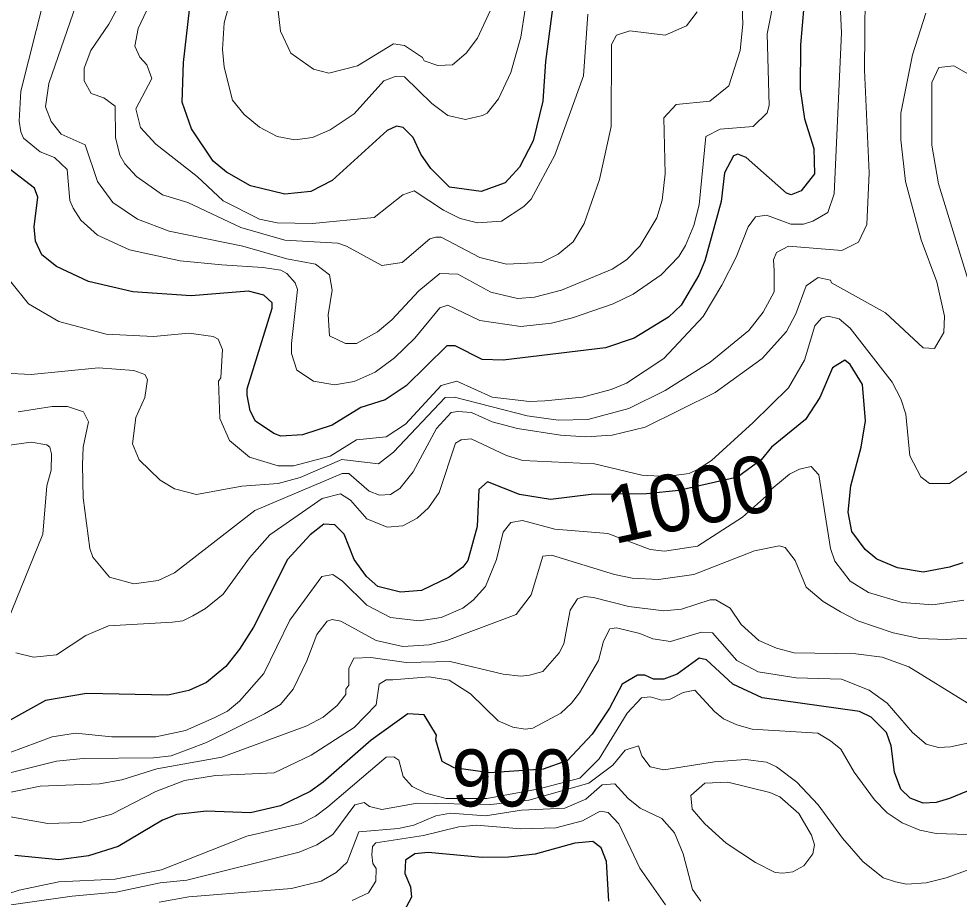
# Model space of a CAD drawing. Extents: x 423 to 448.8, y 7456.3 to 7484.
# Drawn here: x 424.12 to 425.439, y 7464.022 to 7465.258 of the extents above; entities that cross this region are included whole.
import ezdxf
from ezdxf.enums import TextEntityAlignment as Align

# ---------------------------------------------------------------- set-up
doc = ezdxf.new("R2010")
doc.units = 0
doc.header["$LTSCALE"] = 0.032
doc.layers.add('1', color=7, linetype='Continuous', lineweight=25)
doc.layers.add('2', color=7, linetype='Continuous', lineweight=13)
doc.layers.add('61', color=7, linetype='Continuous')

msp = doc.modelspace()

# ---------------------------------------------------------------- linework, layer by layer
at = {"layer": '1'}
for points in [[(425.2237, 7465.303), (425.2168, 7465.221), (425.216, 7465.1591), (425.2222, 7465.1173), (425.2353, 7465.0756), (425.2361, 7465.04), (425.2175, 7465.016), (425.2036, 7465.0106), (425.1967, 7465.0129), (425.1402, 7465.0631), (425.1286, 7465.0678), (425.1224, 7465.0655), (425.11, 7465.0415), (425.1054, 7465.0013), (425.0822, 7464.9178), (425.0737, 7464.8977), (425.0489, 7464.8559), (425.0311, 7464.8388), (424.9832, 7464.8095), (424.943, 7464.7956), (424.7991, 7464.7785), (424.7697, 7464.7793), (424.7318, 7464.7987), (424.7202, 7464.7987), (424.663, 7464.7422), (424.6336, 7464.7229), (424.5996, 7464.712), (424.5593, 7464.6873), (424.5176, 7464.6734), (424.4874, 7464.6718), (424.4774, 7464.6756), (424.4518, 7464.6927), (424.4441, 7464.7074), (424.4402, 7464.7291), (424.4402, 7464.7383), (424.475, 7464.8513), (424.475, 7464.859), (424.4634, 7464.8698), (424.4418, 7464.8752), (424.3613, 7464.869), (424.2794, 7464.8745), (424.2175, 7464.8891), (424.1726, 7464.91), (424.1517, 7464.9263), (424.1432, 7464.9456), (424.1409, 7464.9657), (424.1463, 7465.0075), (424.1416, 7465.0198), (424.1076, 7465.0462)], [(424.871, 7465.2906), (424.8587, 7465.1978), (424.8548, 7465.1421), (424.8416, 7465.0864), (424.8223, 7465.0493), (424.8022, 7465.0276), (424.7682, 7465.0152), (424.7241, 7465.0214), (424.6978, 7465.0477), (424.6839, 7465.0678), (424.673, 7465.091), (424.6591, 7465.1049), (424.6498, 7465.1072), (424.6366, 7465.1011), (424.5593, 7465.0307), (424.5292, 7465.0152), (424.4928, 7465.0113), (424.4449, 7465.023), (424.4108, 7465.0423), (424.3922, 7465.0577), (424.3621, 7465.1034), (424.3489, 7465.1405), (424.3505, 7465.1962), (424.359, 7465.2705)], [(425.4442, 7464.4939), (425.4256, 7464.4877), (425.3885, 7464.4808), (425.3529, 7464.4869), (425.3235, 7464.4993), (425.3073, 7464.5125), (425.2887, 7464.538), (425.2833, 7464.5651), (425.2872, 7464.6022), (425.3019, 7464.6563), (425.308, 7464.6935), (425.3034, 7464.7445), (425.2864, 7464.7723), (425.2786, 7464.7785), (425.2616, 7464.7677), (425.2438, 7464.726), (425.2237, 7464.695), (425.1758, 7464.6563), (425.1614, 7464.6384), (425.128, 7464.614), (425.046, 7464.5953), (425.0006, 7464.5906), (424.9229, 7464.5898), (424.8656, 7464.5828), (424.8223, 7464.5898), (424.7775, 7464.6076), (424.7651, 7464.5968), (424.7628, 7464.545), (424.7496, 7464.497), (424.7426, 7464.4877), (424.7233, 7464.4738), (424.6846, 7464.4552), (424.6553, 7464.4529), (424.6235, 7464.4606), (424.6073, 7464.4746), (424.5903, 7464.4986), (424.5763, 7464.5341), (424.5632, 7464.5473), (424.5477, 7464.5481), (424.5284, 7464.5333), (424.4967, 7464.4986), (424.4487, 7464.4034), (424.4294, 7464.3725), (424.41, 7464.3485), (424.383, 7464.326), (424.3582, 7464.3145), (424.3289, 7464.3083), (424.2144, 7464.3106), (424.1571, 7464.3005), (424.069, 7464.2518)], [(425.0744, 7464.3601), (425.0435, 7464.3377), (425.025, 7464.3307), (425.0102, 7464.3307), (424.9979, 7464.3361), (424.9878, 7464.3361), (424.9662, 7464.3237), (424.9484, 7464.2897), (424.9244, 7464.2533), (424.8896, 7464.2162), (424.8555, 7464.2043), (424.7801, 7464.1989), (424.7304, 7464.2061), (424.7139, 7464.2151), (424.7046, 7464.2454), (424.7055, 7464.2518), (424.6885, 7464.2804), (424.6653, 7464.282), (424.6142, 7464.2448), (424.5469, 7464.186), (424.5284, 7464.1729), (424.4866, 7464.1528), (424.4449, 7464.1428), (424.383, 7464.1451), (424.3412, 7464.1404), (424.3211, 7464.1327), (424.2592, 7464.0955), (424.2175, 7464.0824), (424.1757, 7464.077), (424.1138, 7464.0832)], [(425.4813, 7464.1861), (425.4256, 7464.1629), (425.4071, 7464.1575), (425.3885, 7464.1567), (425.3707, 7464.1636), (425.3575, 7464.176), (425.3483, 7464.2), (425.3436, 7464.2371), (425.3374, 7464.2557), (425.3157, 7464.2773), (425.2995, 7464.2851), (425.1626, 7464.3044), (425.1216, 7464.3237), (425.0845, 7464.3578), (425.0744, 7464.3601)], [(424.9476, 7464.019), (424.9445, 7464.0747), (424.9368, 7464.094), (424.9252, 7464.1025), (424.8997, 7464.1002), (424.844, 7464.0847), (424.8069, 7464.0809), (424.7697, 7464.0801), (424.6939, 7464.0871), (424.6754, 7464.0855), (424.6622, 7464.0763), (424.6614, 7464.0577), (424.6692, 7464.0391), (424.6707, 7464.0244), (424.6599, 7464.0043)]]:
    msp.add_lwpolyline(points, dxfattribs=at)
at = {"layer": '2'}
for points in [[(424.4835, 7465.2689), (424.4866, 7465.2403), (424.5013, 7465.2093), (424.533, 7465.1869), (424.5547, 7465.1815), (424.5949, 7465.1915), (424.6452, 7465.2225), (424.6606, 7465.2202), (424.6862, 7465.2032), (424.6885, 7465.1985), (424.7078, 7465.1923), (424.728, 7465.1931), (424.7473, 7465.2094), (424.7635, 7465.2303), (424.8331, 7465.3811)], [(424.4247, 7465.3138), (424.4077, 7465.2519), (424.4054, 7465.2148), (424.4077, 7465.19), (424.4193, 7465.1436), (424.4356, 7465.1235), (424.4573, 7465.1057), (424.482, 7465.0926), (424.5068, 7465.0879), (424.5315, 7465.091), (424.5563, 7465.1018), (424.5903, 7465.1243), (424.632, 7465.1707), (424.6475, 7465.1769), (424.6606, 7465.1761), (424.6993, 7465.139), (424.7218, 7465.1219), (424.7465, 7465.1165), (424.7705, 7465.1219), (424.7767, 7465.125), (424.7929, 7465.1452), (424.8099, 7465.1823), (424.8239, 7465.2318), (424.8424, 7465.3501)], [(425.308, 7465.3416), (425.3065, 7465.1854), (425.3127, 7465.0415), (425.3096, 7464.9688), (425.298, 7464.9441), (425.2748, 7464.9325), (425.1997, 7464.9386), (425.1827, 7464.9294), (425.1789, 7464.9193), (425.1796, 7464.9039), (425.1796, 7464.8745), (425.1641, 7464.8458), (425.1441, 7464.8203), (425.0899, 7464.7755), (425.0265, 7464.736), (424.9755, 7464.7105), (424.9182, 7464.695), (424.8765, 7464.6942), (424.8332, 7464.7004), (424.7311, 7464.7267), (424.7179, 7464.7259), (424.6452, 7464.6494), (424.6243, 7464.6331), (424.5727, 7464.6389), (424.5145, 7464.6138), (424.4835, 7464.6053), (424.4325, 7464.6014), (424.3691, 7464.5898), (424.3381, 7464.5976), (424.318, 7464.6099), (424.2886, 7464.6385), (424.2793, 7464.6609), (424.284, 7464.6981), (424.2963, 7464.7259), (424.3002, 7464.7515), (424.2964, 7464.7584), (424.2809, 7464.7638), (424.2314, 7464.7677), (424.137, 7464.7584), (424.0999, 7464.76)], [(425.2709, 7465.3091), (425.274, 7465.238), (425.2639, 7465.0121), (425.2547, 7464.9858), (425.2338, 7464.9734), (425.2206, 7464.9696), (425.2029, 7464.9696), (425.1688, 7464.9819), (425.1534, 7464.9796), (425.1433, 7464.9657), (425.1263, 7464.9232), (425.1062, 7464.8837), (425.0799, 7464.8396), (425.025, 7464.7809), (424.9724, 7464.746), (424.9507, 7464.7375), (424.9105, 7464.7267), (424.8579, 7464.7213), (424.8362, 7464.7205), (424.7837, 7464.7267), (424.7341, 7464.7491), (424.7124, 7464.7429), (424.6622, 7464.6888), (424.6351, 7464.671), (424.5934, 7464.6664), (424.5563, 7464.6439), (424.5052, 7464.63), (424.4835, 7464.63), (424.4433, 7464.6424), (424.4154, 7464.6656), (424.4015, 7464.6966), (424.4, 7464.7492), (424.4031, 7464.7538), (424.4054, 7464.7932), (424.3992, 7464.8079), (424.3923, 7464.8118), (424.3582, 7464.8164), (424.3087, 7464.8118), (424.2422, 7464.8149), (424.1757, 7464.8327), (424.1331, 7464.8574), (424.1084, 7464.8884)], [(424.8973, 7464.9448), (424.8764, 7464.9271), (424.8533, 7464.9154), (424.8038, 7464.9131), (424.7666, 7464.9224), (424.7125, 7464.951), (424.7048, 7464.951), (424.6962, 7464.9487), (424.6576, 7464.9154), (424.629, 7464.9115), (424.5795, 7464.9386), (424.5671, 7464.9425), (424.4928, 7464.9471), (424.431, 7464.9649), (424.3567, 7464.9997), (424.3211, 7465.0106), (424.2847, 7465.0361), (424.2685, 7465.0539), (424.2615, 7465.0663), (424.2553, 7465.091), (424.2546, 7465.1351), (424.2391, 7465.1467), (424.2213, 7465.1529), (424.2113, 7465.1707), (424.2113, 7465.1885), (424.2205, 7465.2132), (424.2461, 7465.2504), (424.2724, 7465.2999)], [(425.134, 7465.2999), (425.1355, 7465.2504), (425.1317, 7465.2132), (425.1162, 7465.1637), (425.0891, 7465.1421), (425.042, 7465.1374), (425.0249, 7465.1189), (425.0265, 7465.04), (425.0226, 7465.0029), (425.0149, 7464.9781), (424.9909, 7464.9386), (424.9724, 7464.9193), (424.9523, 7464.9061), (424.8811, 7464.8768), (424.8432, 7464.8667), (424.8192, 7464.8652), (424.7821, 7464.8737), (424.7357, 7464.8992), (424.7102, 7464.9), (424.6808, 7464.876), (424.6429, 7464.835), (424.6227, 7464.818), (424.5933, 7464.8018), (424.5779, 7464.8018), (424.5554, 7464.8125), (424.5539, 7464.842), (424.5593, 7464.8768), (424.5555, 7464.8984), (424.5361, 7464.9131), (424.4959, 7464.9208), (424.434, 7464.9386), (424.3304, 7464.9595)], [(425.1812, 7465.2937), (425.1696, 7465.2364), (425.1727, 7465.1359), (425.1696, 7465.1258), (425.1503, 7465.1065), (425.1039, 7465.1026), (425.0837, 7465.0925), (425.0745, 7464.9967), (425.0667, 7464.9673), (425.0551, 7464.9394), (425.0458, 7464.924), (425.0211, 7464.8984), (424.9817, 7464.8713), (424.9538, 7464.8574), (424.8966, 7464.8381), (424.8672, 7464.8303), (424.8239, 7464.8257), (424.7666, 7464.8342), (424.7218, 7464.8559), (424.7102, 7464.852), (424.6753, 7464.8095), (424.6467, 7464.7816), (424.6197, 7464.7615), (424.5903, 7464.7484), (424.5624, 7464.7437), (424.533, 7464.7491), (424.5098, 7464.7646), (424.5021, 7464.7878), (424.5021, 7464.8018), (424.5106, 7464.8776), (424.5075, 7464.8868), (424.4959, 7464.9), (424.4874, 7464.9046), (424.4619, 7464.9085), (424.4047, 7464.9123), (424.3459, 7464.9177), (424.2747, 7464.9332), (424.2299, 7464.9541), (424.2066, 7464.975), (424.1958, 7464.992), (424.1912, 7465.0028), (424.1873, 7465.0462), (424.1695, 7465.0632), (424.1494, 7465.0709), (424.1262, 7465.0902), (424.1223, 7465.0988), (424.12, 7465.1142)], [(424.12, 7465.1142), (424.1223, 7465.156), (424.1548, 7465.2844)], [(424.3304, 7464.9595), (424.2863, 7464.9765), (424.2515, 7464.9998), (424.2298, 7465.0292), (424.2128, 7465.0809), (424.1788, 7465.0957), (424.1648, 7465.1134), (424.1571, 7465.1343), (424.1617, 7465.1668), (424.2043, 7465.2906)], [(425.3923, 7465.2658), (425.3738, 7465.2071), (425.3575, 7465.1251), (425.3575, 7465.0879), (425.3637, 7465.0292), (425.3861, 7464.9472), (425.4078, 7464.8884), (425.4186, 7464.8404), (425.4178, 7464.8172), (425.4047, 7464.7948), (425.3885, 7464.7956), (425.3359, 7464.845), (425.2601, 7464.8868), (425.2586, 7464.8907), (425.2415, 7464.8945), (425.2245, 7464.8829), (425.2098, 7464.8435), (425.1967, 7464.8187), (425.1626, 7464.7809), (425.0969, 7464.7329), (424.9987, 7464.6842), (424.9523, 7464.6733), (424.9151, 7464.671), (424.8796, 7464.6733), (424.8192, 7464.6826), (424.7837, 7464.6919), (424.755, 7464.705), (424.7357, 7464.7066), (424.7264, 7464.705), (424.7055, 7464.6826), (424.673, 7464.6215), (424.6545, 7464.5983), (424.6413, 7464.5898), (424.6259, 7464.589), (424.6111, 7464.5945), (424.5825, 7464.6192), (424.5733, 7464.6192), (424.451, 7464.5674), (424.3381, 7464.48), (424.3149, 7464.4692), (424.2809, 7464.4645), (424.2469, 7464.4738), (424.2236, 7464.5017), (424.219, 7464.514), (424.2097, 7464.5852), (424.2089, 7464.6316), (424.2097, 7464.6563), (424.2174, 7464.6919), (424.2105, 7464.7058), (424.188, 7464.7136), (424.1664, 7464.7135), (424.1185, 7464.7058)], [(424.9182, 7465.2643), (424.912, 7465.1777), (424.8718, 7465.0663), (424.8386, 7465.0044), (424.8285, 7464.9943), (424.7968, 7464.9735), (424.7635, 7464.9711), (424.7388, 7464.9773), (424.7155, 7464.9889), (424.6746, 7465.016), (424.6583, 7465.0106), (424.6181, 7464.9788), (424.5315, 7464.9704), (424.482, 7464.9711), (424.4573, 7464.9765), (424.4062, 7465.0021), (424.3698, 7465.0361), (424.3118, 7465.0817), (424.2902, 7465.1049), (424.284, 7465.1313), (424.3064, 7465.1738), (424.2994, 7465.1931), (424.2894, 7465.2039), (424.2824, 7465.2194), (424.287, 7465.2442), (424.2987, 7465.2689)], [(425.0714, 7465.2673), (425.0567, 7465.248), (425.0265, 7465.2349), (424.977, 7465.241), (424.9584, 7465.2349), (424.9515, 7465.2217), (424.9507, 7465.1065), (424.9344, 7465.0322), (424.9128, 7464.9704), (424.8973, 7464.9448)], [(425.486, 7465.1606), (425.4318, 7465.1915), (425.4109, 7465.1892), (425.4009, 7465.1684), (425.4009, 7465.0802), (425.4101, 7465.0261), (425.465, 7464.8482)], [(425.4565, 7464.6262), (425.4256, 7464.6053), (425.3978, 7464.6053), (425.3854, 7464.6146), (425.3699, 7464.644), (425.3645, 7464.7028), (425.3576, 7464.7244), (425.3451, 7464.7476), (425.2864, 7464.8234), (425.2709, 7464.8365), (425.2554, 7464.8404), (425.2462, 7464.8373), (425.2369, 7464.8265), (425.2222, 7464.7786), (425.1997, 7464.7398), (425.1503, 7464.6911), (425.0915, 7464.6377), (425.0729, 7464.6254), (425.0605, 7464.6192), (425.0281, 7464.6153), (424.994, 7464.6169), (424.9275, 7464.6331), (424.827, 7464.6378), (424.8038, 7464.6447), (424.7543, 7464.6679), (424.7403, 7464.6664), (424.7326, 7464.6617), (424.7094, 7464.5929), (424.6947, 7464.5712), (424.6785, 7464.5565), (424.6583, 7464.5457), (424.6367, 7464.5442), (424.6081, 7464.5558), (424.5849, 7464.5821), (424.5709, 7464.5906), (424.5454, 7464.5844), (424.4719, 7464.5333), (424.4433, 7464.5009), (424.4062, 7464.4498), (424.3815, 7464.4297), (424.3636, 7464.4196), (424.3497, 7464.4127), (424.335, 7464.4104), (424.2453, 7464.4057), (424.2136, 7464.3918), (424.1726, 7464.3647), (424.1401, 7464.3616), (424.1153, 7464.3678)], [(424.1037, 7464.4119), (424.1532, 7464.5341), (424.1587, 7464.6022), (424.1649, 7464.6239), (424.1656, 7464.6471), (424.1633, 7464.6563), (424.1587, 7464.6594), (424.137, 7464.6633), (424.0581, 7464.6524)], [(425.4457, 7464.4413), (425.4024, 7464.4351), (425.3591, 7464.4382), (425.3119, 7464.4521), (425.2864, 7464.4684), (425.2647, 7464.4962), (425.2585, 7464.514), (425.2423, 7464.6177), (425.2315, 7464.6292), (425.2152, 7464.6254), (425.2013, 7464.6184), (425.168, 7464.5906), (425.169, 7464.588), (425.1353, 7464.558), (425.0722, 7464.5175), (425.0257, 7464.5103), (425.0054, 7464.5125), (424.9461, 7464.5349), (424.8718, 7464.5411), (424.8262, 7464.5534), (424.8099, 7464.5504), (424.7991, 7464.5372), (424.7898, 7464.4986), (424.7744, 7464.4606), (424.7574, 7464.4413), (424.7426, 7464.4305), (424.7125, 7464.4173), (424.6816, 7464.4127), (424.6413, 7464.4173), (424.608, 7464.4343), (424.574, 7464.4684), (424.5601, 7464.4776)], [(424.0489, 7464.1845), (424.1726, 7464.2155), (424.2097, 7464.2193), (424.3087, 7464.2201), (424.3335, 7464.2232), (424.383, 7464.2417), (424.4642, 7464.282), (424.4866, 7464.2951), (424.5044, 7464.3168), (424.5238, 7464.3562), (424.5376, 7464.3934), (424.5524, 7464.4119), (424.5593, 7464.4142), (424.5717, 7464.4119), (424.6212, 7464.3848), (424.6583, 7464.3763), (424.6955, 7464.3786), (424.7202, 7464.3848), (424.8176, 7464.4212), (424.8385, 7464.4491), (424.8548, 7464.5032), (424.8672, 7464.5047), (424.9554, 7464.4776), (424.9801, 7464.4723), (425.0172, 7464.4707), (425.0667, 7464.4776), (425.1518, 7464.5109), (425.1866, 7464.5179), (425.1951, 7464.5155), (425.209, 7464.497), (425.2245, 7464.4599), (425.2485, 7464.4397), (425.2725, 7464.425), (425.2972, 7464.4127), (425.3467, 7464.3957), (425.3839, 7464.3879), (425.421, 7464.3864), (425.4581, 7464.3887)], [(424.5601, 7464.4776), (424.5446, 7464.4746), (424.4998, 7464.4135), (424.4634, 7464.3384), (424.4294, 7464.2997), (424.4124, 7464.2858), (424.3938, 7464.2765), (424.3536, 7464.2587), (424.3118, 7464.2495), (424.25, 7464.2495), (424.1989, 7464.2549), (424.1664, 7464.2495), (424.1061, 7464.227)], [(424.9755, 7464.4328), (424.926, 7464.4452), (424.9136, 7464.4467), (424.9035, 7464.4436), (424.8934, 7464.4274), (424.8842, 7464.3802), (424.878, 7464.3678), (424.8548, 7464.3415), (424.8362, 7464.3361), (424.8239, 7464.3346), (424.7991, 7464.3377), (424.7249, 7464.3554), (424.663, 7464.3539), (424.6135, 7464.3608), (424.5895, 7464.3601), (424.5825, 7464.3454), (424.5825, 7464.3222), (424.5787, 7464.3168), (424.5787, 7464.309), (424.5663, 7464.2936), (424.5469, 7464.2773), (424.5238, 7464.2649), (424.4047, 7464.2209), (424.3134, 7464.2046), (424.2639, 7464.1891), (424.2329, 7464.1837), (424.1494, 7464.1806), (424.0829, 7464.1667)], [(425.4504, 7464.2974), (425.3684, 7464.3477), (425.3313, 7464.3616), (425.2941, 7464.3663), (425.2075, 7464.3678), (425.1828, 7464.374), (425.158, 7464.3848), (425.1332, 7464.4073), (425.1178, 7464.4304), (425.0977, 7464.4421), (425.0899, 7464.4421), (425.0497, 7464.4289), (425.025, 7464.4266), (424.9755, 7464.4328)], [(424.0891, 7464.1404), (424.1602, 7464.1281), (424.2066, 7464.1296), (424.25, 7464.1412), (424.3118, 7464.1729), (424.3521, 7464.1884), (424.3954, 7464.1954), (424.4781, 7464.1992), (424.53, 7464.224), (424.5902, 7464.2626), (424.6212, 7464.2944), (424.6251, 7464.3238), (424.6351, 7464.3299), (424.6444, 7464.3299), (424.6955, 7464.3338), (424.7233, 7464.3291), (424.7535, 7464.3098), (424.7921, 7464.2719), (424.813, 7464.2634), (424.8301, 7464.2603), (424.8408, 7464.2618), (424.8803, 7464.2827), (424.895, 7464.2967), (424.9066, 7464.3113), (424.9329, 7464.357), (424.9399, 7464.3841), (424.9491, 7464.4011), (424.9585, 7464.4026), (424.9909, 7464.3949), (425.0095, 7464.3871), (425.0343, 7464.3833), (425.0776, 7464.3964), (425.093, 7464.3957), (425.1271, 7464.357), (425.1572, 7464.3407), (425.2106, 7464.3323), (425.274, 7464.3307), (425.3127, 7464.3152), (425.3382, 7464.2967), (425.3738, 7464.2557), (425.3931, 7464.2394), (425.4102, 7464.2348), (425.4272, 7464.2355), (425.4535, 7464.241)], [(425.4504, 7464.1126), (425.4071, 7464.1141), (425.3839, 7464.1188), (425.3591, 7464.1288), (425.3382, 7464.1428), (425.3204, 7464.1613), (425.2918, 7464.2), (425.2732, 7464.2325), (425.2586, 7464.2441), (425.2407, 7464.2549), (425.1487, 7464.2603), (425.1271, 7464.2665), (425.1085, 7464.275), (425.0961, 7464.2851), (425.0683, 7464.3152), (425.052, 7464.3121), (425.0327, 7464.3021), (425.0219, 7464.3013), (425.0056, 7464.3059), (424.9932, 7464.3044), (424.9731, 7464.2827), (424.9341, 7464.2186), (424.9071, 7464.1915), (424.85, 7464.1765), (424.7765, 7464.163), (424.7194, 7464.1629), (424.6908, 7464.1706), (424.6715, 7464.1799), (424.6591, 7464.1938), (424.6529, 7464.217), (424.6459, 7464.2216), (424.6351, 7464.2209), (424.5532, 7464.1513), (424.5361, 7464.1381), (424.516, 7464.128), (424.4394, 7464.1102), (424.3196, 7464.0631), (424.2546, 7464.0499), (424.1757, 7464.0461), (424.12, 7464.0345), (424.0427, 7464.0097)], [(424.0323, 7464.0032), (424.1943, 7464.0259), (424.2562, 7464.0314), (424.318, 7464.0445), (424.3552, 7464.0484), (424.5129, 7464.0878), (424.5377, 7464.0979), (424.5601, 7464.1126), (424.591, 7464.1544), (424.6042, 7464.1574), (424.6119, 7464.152), (424.629, 7464.1474), (424.6785, 7464.1567), (424.782, 7464.1545), (424.8353, 7464.1605), (424.9193, 7464.1845), (424.9531, 7464.21), (424.9704, 7464.231), (424.9894, 7464.2371), (424.994, 7464.2232), (425.0056, 7464.2077), (425.025, 7464.2031), (425.0961, 7464.2147), (425.1394, 7464.2178), (425.1688, 7464.2139), (425.1828, 7464.2077), (425.2113, 7464.186), (425.2415, 7464.1543), (425.2755, 7464.1072), (425.3042, 7464.0747), (425.3328, 7464.0515), (425.3498, 7464.0461), (425.3653, 7464.043), (425.3931, 7464.0445), (425.421, 7464.0515), (425.4782, 7464.0724)], [(424.3165, 7464.0174), (424.3582, 7464.0252), (424.5021, 7464.0368), (424.5439, 7464.0468), (424.5647, 7464.0592), (424.5802, 7464.0739), (424.5965, 7464.1164), (424.6522, 7464.1211), (424.6738, 7464.1257), (424.7047, 7464.1389), (424.7252, 7464.1427), (424.7744, 7464.1389), (424.8249, 7464.1468), (424.8857, 7464.1497), (424.9151, 7464.1621), (424.9383, 7464.1822), (424.9561, 7464.1837), (424.9747, 7464.1629), (424.9917, 7464.1497), (425.0219, 7464.135), (425.0396, 7464.1149), (425.052, 7464.0855), (425.0651, 7464.0352), (425.0768, 7464.019)], [(425.0273, 7464.0136), (424.9909, 7464.0654), (424.9615, 7464.1273), (424.9468, 7464.1435), (424.9352, 7464.1451), (424.9105, 7464.1319), (424.8734, 7464.1219), (424.8239, 7464.1203), (424.762, 7464.1257), (424.7372, 7464.1234), (424.6877, 7464.111), (424.6204, 7464.101), (424.6158, 7464.0956), (424.615, 7464.084), (424.6166, 7464.0716), (424.6212, 7464.0646), (424.6204, 7464.0469), (424.6104, 7464.0306), (424.5872, 7464.0198)]]:
    msp.add_lwpolyline(points, dxfattribs=at)
msp.add_lwpolyline([(425.1534, 7464.0731), (425.1124, 7464.1002), (425.0822, 7464.1273), (425.0644, 7464.1482), (425.0628, 7464.1675), (425.0822, 7464.1845), (425.1147, 7464.186), (425.1735, 7464.1714), (425.1874, 7464.1652), (425.2144, 7464.142), (425.2322, 7464.1118), (425.2361, 7464.0979), (425.2338, 7464.0855), (425.2214, 7464.0685), (425.206, 7464.06), (425.192, 7464.0584), (425.1812, 7464.0592)], close=True, dxfattribs=at)

# ---------------------------------------------------------------- texts
at = {"layer": '61'}
msp.add_text('1000', height=0.08, rotation=12.246, dxfattribs=at).set_placement((425.0709, 7464.5452), align=Align.CENTER)
at = {"layer": '61', "width": 0.95}
msp.add_text('900', height=0.08, dxfattribs=at).set_placement((424.8118, 7464.1519), align=Align.CENTER)

doc.saveas('drawing.dxf')
